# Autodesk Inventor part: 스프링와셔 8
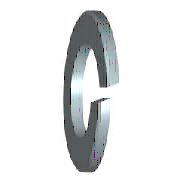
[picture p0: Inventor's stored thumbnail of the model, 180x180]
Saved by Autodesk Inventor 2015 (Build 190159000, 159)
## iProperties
IsCustomPart: 1
Created: 2012-02
Part Number: 스프링와셔 8
Material: 강철, 연강
Description: 스프링 잠금 와셔
Document SubType Name: Modeling
Standard: KS B 1324
Designer: mduedu
Standards Organization: KS
Language: ko-KR
Size Designation: 번호 3 - 8
Categories: <MemberInstance><Categories><Category DisplayName="조임쇠" InternalName="e4da775c-781d-43d5-af7c-5136215cf5a6" Mnemonic="FSTN"><Category DisplayName="와셔" InternalN
Density: 7.86 g/cm^3
Mass: 2.27751 g
Surface Area: 4.25113 cm^2
Volume: 0.289759 cm^3
Appearance: 파란색 - 벽 페인트 - 광택
Author: mduedu
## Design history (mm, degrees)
sketch "스케치1"
  geometry: C1 r 7.4 at (0, 0); C2 r 4.1 at (0, 0); 1 further point
  constraints: 2 centre point, 2 coincident
  dimensions: "d0" = 8.2 diameter of C2 (= SD1); "d1" = 14.8 diameter of C1 (= SD2)
extrude "본체" new body sketch "스케치1" distance "d2" = 2.5 (= SD); taper "d3" = 0 deg
sketch "스케치2"
  geometry: L1 (0, -4.1)-(0, 4.1) reference; L2 (2.5, 7.4)-(2.5, -7.4) reference; L3 (-1.2, 0)-(7.2, 0) reference; L4 (0, -0.5)-(2.5, 0.41); L5 (0, 0.5)-(2.5, 1.41)
  constraints: 4 end point, 4 point on line, 1 parallel
  dimensions: "d4" = 0.5 distance from line of L3 L4.start (= 0.2 x SD); "d5" = 0.5 distance from line of L3 L5.start (= 0.2 x SD); "d6" = 70 deg angle of L2 L4 (= FAWI)
extrude "절단부" cut sketch "스케치2" stored distance "d7" = 2.5 (= SD); taper "d8" = 0 deg
workaxis "Work Axis1"
workplane "Work Plane1"
body "Solid1"
other parameters: "SD1" = 8.2 [user parameter; used in 1 equation term], "SD2" = 14.8 [user parameter; used in 1 equation term], "SD" = 2.5 [user parameter; used in 4 equation terms], "FAWI" = 70 deg [user parameter; used in 1 equation term], "d9" = 0, "d10" = 0, "d11" = 0, "d12" = 0, "SDI" = 3.3 [user parameter], "NND" = 8 [user parameter]
